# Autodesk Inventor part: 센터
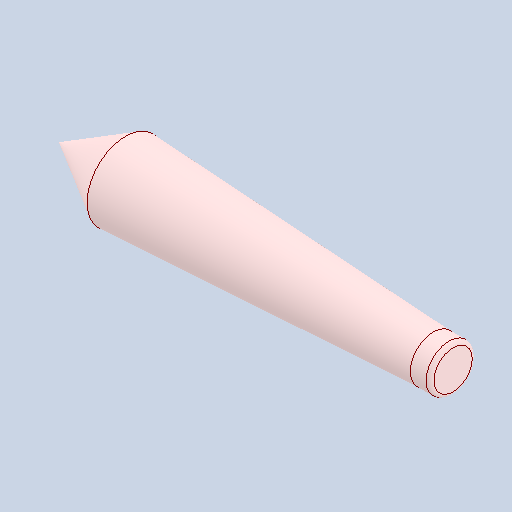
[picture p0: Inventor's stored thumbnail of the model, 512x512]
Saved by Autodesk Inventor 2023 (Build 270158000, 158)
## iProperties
Created: 2024-07
Part Number: 센터
Material: 강철, 합금
Document SubType Name: Modeling
Designer: home
Density: 7.73 g/cm^3
Appearance: 기본값
Author: jhkim
Sending System: Autodesk Inventor 2025
Preprocessor: ST-DEVELOPER v20
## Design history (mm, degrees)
feature "솔리드1"
node "솔리드2"
